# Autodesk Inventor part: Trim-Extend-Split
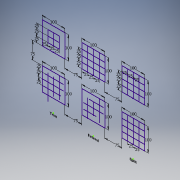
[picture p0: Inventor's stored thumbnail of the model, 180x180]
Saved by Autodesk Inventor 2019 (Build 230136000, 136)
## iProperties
Created: 2018-11
Part Number: Trim-Extend-Split
Material: Generic
Document SubType Name: Modeling
Designer: Synergysoft
Density: 1 g/cm^3
Appearance: Default
Author: Synergysoft
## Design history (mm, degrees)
sketch "Sketch1"
  geometry: L1 (0, 0)-(100, 0); L2 (100, 0)-(100, 100); L3 (100, 100)-(0, 100); L4 (0, 100)-(0, 0); L5 (25, 75)-(25, 25); L6 (50, 75)-(50, 25); L7 (75, 75)-(75, 25); L8 (25, 75)-(75, 75); L9 (25, 50)-(75, 50); L10 (25, 25)-(75, 25); L11 (175, 0)-(275, 0); L12 (275, 0)-(275, 100); L13 (275, 100)-(175, 100); L14 (175, 100)-(175, 0); L15 (200, 100)-(200, 0); L16 (225, 100)-(225, 0); L17 (250, 100)-(250, 0); L18 (175, 75)-(275, 75); L19 (175, 50)-(275, 50); L20 (175, 25)-(275, 25); L21 (350, 0)-(450, 0); L22 (450, 0)-(450, 100); L23 (450, 100)-(350, 100); L24 (350, 100)-(350, 0); L25 (0, -175)-(100, -175); L26 (100, -175)-(100, -75); L27 (100, -75)-(0, -75); L28 (0, -75)-(0, -175); L29 (25, -90.438)-(25, -198.932); L30 (50, -92.487)-(50, -167.719); L31 (75, -75)-(75, -167.719); L32 (11.931, -100)-(94.141, -100); L33 (-2.034, -125)-(93.671, -125); L34 (4.68, -150)-(82.406, -150); L35 (350, -75)-(350, -175); L36 (450, -75)-(350, -75); L37 (350, -175)-(450, -175); L38 (450, -175)-(450, -75); L39 (175, -75)-(175, -175); L40 (200, -97.084)-(200, -177.084); L41 (225, -100.387)-(225, -153.277); L42 (180.886, -150)-(238.201, -150); L43 (250, -75)-(250, -167.719); L44 (180.886, -125)-(269.877, -125); L45 (206.524, -100)-(269.877, -100); L46 (175, -175)-(275, -175); L47 (275, -75)-(175, -75); L48 (275, -175)-(275, -75); L49 (17.594, -230.77)-(82.406, -230.77); L50 (82.406, -230.77)-(82.406, -245.5); L51 (82.406, -245.5)-(17.594, -245.5); L52 (17.594, -245.5)-(17.594, -230.77); L53 (192.594, -245.5)-(192.594, -230.77); L54 (192.594, -230.77)-(257.406, -230.77); L55 (257.406, -230.77)-(257.406, -245.5); L56 (257.406, -245.5)-(192.594, -245.5); L57 (367.594, -245.5)-(367.594, -230.77); L58 (367.594, -230.77)-(432.406, -230.77); L59 (432.406, -230.77)-(432.406, -245.5); L60 (432.406, -245.5)-(367.594, -245.5); L61 (425, 100)-(425, 75); L62 (400, 100)-(400, 75); L63 (375, 100)-(375, 75); L64 (350, 50)-(375, 50)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; 6 further points
  constraints: 154 end point, 92 parallel, 18 collinear, 15 horizontal, 15 midpoint, 14 point on line, 6 perpendicular, 3 vertical alignment, 6 other
  dimensions: "d2" = 100 distance of L3.end L2.end; "d3" = 100 distance of L2.end L1.end; "d13" = 100 distance of L13.end L12.end; "d14" = 100 distance of L12.end L11.end; "d15" = 100 distance of L23.end L22.end; "d16" = 100 distance of L22.end L21.end; "d17" = 75 distance between parallel lines of L14 L2; "d18" = 75 distance between parallel lines of L24 L12; "d19" = 100 distance of L27.end L26.end; "d20" = 100 distance of L26.end L25.end; "d21" = 100 distance of L39.start L47.start; "d22" = 100 distance of L47.start L46.end; "d23" = 100 distance of L35.start L36.start; "d24" = 100 distance of L36.start L37.end; "d25" = 75 distance between parallel lines of L39 L26; "d26" = 75 distance between parallel lines of L35 L48; "d27" = 75 distance between parallel lines of L27 L1; "d28" = 25 distance between parallel lines of L15 L14; "d29" = 25 distance between parallel lines of L16 L15; "d30" = 25 distance between parallel lines of L17 L16; "d31" = 25 distance between parallel lines of L11 L20; "d32" = 25 distance between parallel lines of L19 L20; "d33" = 25 distance between parallel lines of L19 L18; "d34" = 25 distance between parallel lines of L1 L10; "d35" = 25 distance between parallel lines of L9 L10; "d36" = 25 distance between parallel lines of L8 L9; "d37" = 25 distance between parallel lines of L4 L5; "d38" = 25 distance between parallel lines of L6 L5; "d39" = 25 distance between parallel lines of L6 L7; "d43" = 25 distance between parallel lines of L62 L63; "d44" = 25 distance between parallel lines of L61 L62; "d45" = 25 distance between parallel lines of L64 L66; "d46" = 25 distance between parallel lines of L64 L65; "d47" = 25 distance between parallel lines of L63 L24; "d48" = 25 distance between parallel lines of L66 L21; "d49" = 25 distance between parallel lines of L87 L86; "d50" = 25 distance between parallel lines of L88 L87; "d53" = 25 distance between parallel lines of L27 L32; "d54" = 25 distance between parallel lines of L32 L33; "d55" = 25 distance between parallel lines of L34 L33
